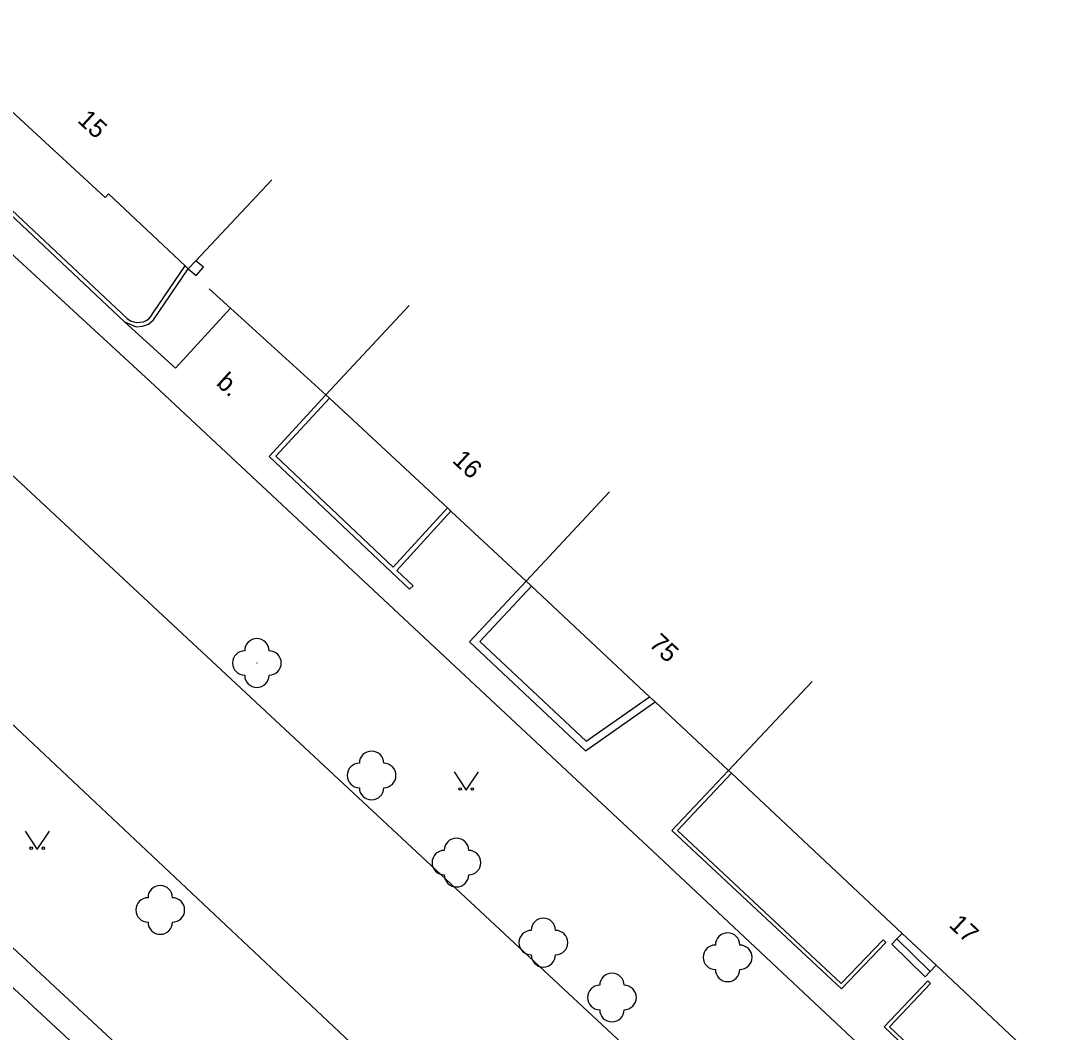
# Model space of a CAD drawing. Extents: x -577457 to -568404, y -1208466 to -1201387.
# Drawn here: x -572983.9 to -572941.19, y -1203285.12 to -1203243.67 of the extents above; entities that cross this region are included whole.
import ezdxf

# ---------------------------------------------------------------- set-up
doc = ezdxf.new("R2010")
doc.units = 0
for name, color, linetype in [('BUDOVY_MĚŘ', 7, 'Continuous'), ('POMOC_POPIS', 7, 'Continuous'), ('ROZHRANÍ_PLOCH', 7, 'Continuous'), ('ZELEŇ', 7, 'Continuous'), ('ZN_DOPLŇKOVÉ', 7, 'Continuous'), ('ZN_KULTUR', 7, 'Continuous'), ('Č_POPIS_ORIENT', 7, 'Continuous')]:
    doc.layers.add(name, color=color, linetype=linetype)

msp = doc.modelspace()

# ---------------------------------------------------------------- linework, layer by layer
at = {"layer": 'BUDOVY_MĚŘ'}
for points in [[(-572987.99, -1203243.67), (-572984.33, -1203247.05), (-572984.47, -1203247.2), (-572980.45, -1203250.91), (-572980.31, -1203250.76), (-572977.17, -1203253.71)], [(-572976.73, -1203253.5), (-572973.62, -1203250.18)], [(-572977.17, -1203253.71), (-572977.04, -1203253.83)], [(-572977.04, -1203253.83), (-572976.73, -1203253.5)], [(-572971.4, -1203259), (-572967.99, -1203255.34)], [(-572971.25, -1203259.14), (-572971.4, -1203259)], [(-572966.42, -1203263.63), (-572971.25, -1203259.14)], [(-572959.78, -1203262.98), (-572963.2, -1203266.63)], [(-572966.28, -1203263.76), (-572966.42, -1203263.63)], [(-572963.2, -1203266.63), (-572966.28, -1203263.76)], [(-572962.98, -1203266.84), (-572963.2, -1203266.63)], [(-572958.14, -1203271.37), (-572962.98, -1203266.84)], [(-572951.48, -1203270.75), (-572954.9, -1203274.4)], [(-572957.91, -1203271.58), (-572958.14, -1203271.37)], [(-572954.9, -1203274.4), (-572957.91, -1203271.58)], [(-572954.78, -1203274.51), (-572954.9, -1203274.4)], [(-572947.79, -1203281.07), (-572954.78, -1203274.51)], [(-572946.4, -1203282.38), (-572947.79, -1203281.07)], [(-572941.31, -1203287.15), (-572946.4, -1203282.38)]]:
    msp.add_lwpolyline(points, dxfattribs=at)
at = {"layer": 'ROZHRANÍ_PLOCH'}
for points in [[(-572996.91, -1203250.52), (-572992.33, -1203245.82), (-572978.62, -1203258.44), (-572957.99, -1203277.72), (-572943.9, -1203290.94), (-572948.47, -1203295.64)], [(-572996.91, -1203250.52), (-572948.47, -1203295.64)], [(-572979.65, -1203256.01), (-572977.56, -1203257.91), (-572975.31, -1203255.45)], [(-572978.48, -1203288.63), (-572997.29, -1203271.18)], [(-572985.5, -1203271.33), (-572970.39, -1203285.54)], [(-572990.07, -1203276.24), (-572974.19, -1203291)], [(-572947.79, -1203281.07), (-572948, -1203281.3)], [(-572948, -1203281.3), (-572948.21, -1203281.51), (-572946.84, -1203282.85), (-572946.64, -1203282.63)], [(-572948, -1203281.3), (-572946.64, -1203282.63)], [(-572946.64, -1203282.63), (-572946.4, -1203282.38)]]:
    msp.add_lwpolyline(points, dxfattribs=at)
at = {"layer": 'ZELEŇ'}
for centre in [(-572974.23, -1203269.99), (-572969.53, -1203274.6), (-572966.05, -1203278.17), (-572978.19, -1203280.11), (-572962.49, -1203281.45), (-572954.94, -1203282.05), (-572959.68, -1203283.7)]:
    msp.add_circle(centre, 0.0005, dxfattribs=at)
for centre, start, end in [((-572974.23, -1203269.49), 0, 180), ((-572974.73, -1203269.99), 90, 270), ((-572973.73, -1203269.99), 270, 90), ((-572974.23, -1203270.49), 180, 360), ((-572969.53, -1203274.1), 0, 180), ((-572970.03, -1203274.6), 90, 270), ((-572969.03, -1203274.6), 270, 90), ((-572969.53, -1203275.1), 180, 360), ((-572966.05, -1203277.67), 0, 180), ((-572966.55, -1203278.17), 90, 270), ((-572965.55, -1203278.17), 270, 90), ((-572966.05, -1203278.67), 180, 360), ((-572978.19, -1203279.61), 0, 180), ((-572978.69, -1203280.11), 90, 270), ((-572977.69, -1203280.11), 270, 90), ((-572978.19, -1203280.61), 180, 360), ((-572962.49, -1203280.95), 0, 180), ((-572962.99, -1203281.45), 90, 270), ((-572961.99, -1203281.45), 270, 90), ((-572954.94, -1203281.55), 0, 180), ((-572955.44, -1203282.05), 90, 270), ((-572954.44, -1203282.05), 270, 90), ((-572962.49, -1203281.95), 180, 360), ((-572959.68, -1203283.2), 0, 180), ((-572954.94, -1203282.55), 180, 360), ((-572960.18, -1203283.7), 90, 270), ((-572959.18, -1203283.7), 270, 90), ((-572959.68, -1203284.2), 180, 360)]:
    msp.add_arc(centre, 0.5, start, end, dxfattribs=at)
at = {"layer": 'ZN_DOPLŇKOVÉ'}
for points in [[(-572985.3, -1203250.71), (-572985.18, -1203250.58), (-572979.54, -1203255.87), (-572979.41, -1203255.96), (-572979.27, -1203256.01), (-572979.15, -1203256.03), (-572979.01, -1203256.02), (-572978.87, -1203256), (-572978.77, -1203255.95), (-572978.66, -1203255.88), (-572978.58, -1203255.79), (-572978.48, -1203255.64), (-572977.17, -1203253.71)], [(-572985.3, -1203250.71), (-572979.65, -1203256.01)], [(-572979.65, -1203256.01), (-572979.17, -1203256.21), (-572978.91, -1203256.19), (-572978.67, -1203256.1), (-572978.46, -1203255.93), (-572977.04, -1203253.83)], [(-572977.04, -1203253.83), (-572976.72, -1203254.11), (-572976.42, -1203253.77), (-572976.73, -1203253.5)], [(-572976.19, -1203254.65), (-572975.31, -1203255.45)], [(-572975.31, -1203255.45), (-572971.4, -1203259)], [(-572971.4, -1203259), (-572973.73, -1203261.52), (-572967.97, -1203266.97), (-572967.83, -1203266.83), (-572968.5, -1203266.2), (-572966.28, -1203263.76)], [(-572966.42, -1203263.63), (-572968.64, -1203266.06), (-572973.45, -1203261.51), (-572971.25, -1203259.14)], [(-572963.2, -1203266.63), (-572965.52, -1203269.12), (-572960.76, -1203273.59), (-572957.91, -1203271.58)], [(-572962.98, -1203266.84), (-572965.1, -1203269.11), (-572960.73, -1203273.2), (-572958.14, -1203271.37)], [(-572954.9, -1203274.4), (-572957.23, -1203276.86), (-572950.27, -1203283.34), (-572948.45, -1203281.44)], [(-572948.45, -1203281.44), (-572948.57, -1203281.33), (-572950.28, -1203283.12), (-572957, -1203276.85), (-572954.78, -1203274.51)], [(-572946.74, -1203283.02), (-572948.53, -1203284.9), (-572943.99, -1203289.23), (-572941.19, -1203287.26)], [(-572941.31, -1203287.15), (-572943.98, -1203289.02), (-572948.3, -1203284.9), (-572946.62, -1203283.13), (-572946.74, -1203283.02)]]:
    msp.add_lwpolyline(points, dxfattribs=at)
at = {"layer": 'ZN_KULTUR'}
for points in [[(-572966.15, -1203274.45), (-572965.65, -1203275.2), (-572965.15, -1203274.45)], [(-572983.73, -1203276.88), (-572983.23, -1203277.63), (-572982.73, -1203276.88)]]:
    msp.add_lwpolyline(points, dxfattribs=at)
for centre in [(-572965.9, -1203275.15), (-572965.4, -1203275.15), (-572983.48, -1203277.58), (-572982.98, -1203277.58)]:
    msp.add_circle(centre, 0.05, dxfattribs=at)

# ---------------------------------------------------------------- texts
at = {"layer": 'POMOC_POPIS'}
msp.add_text(' b.', height=0.75, rotation=317.76, dxfattribs=at).set_placement((-572976.14, -1203258.38))
at = {"layer": 'Č_POPIS_ORIENT'}
for s, rotation, p in [('15', 317.3, (-572981.62, -1203247.79)), ('16', 317.06, (-572966.26, -1203261.73)), ('75', 316.89, (-572958.2, -1203269.26)), ('17', 316.84, (-572945.91, -1203280.77))]:
    msp.add_text(s, height=0.75, rotation=rotation, dxfattribs=at).set_placement(p)

doc.saveas('drawing.dxf')
